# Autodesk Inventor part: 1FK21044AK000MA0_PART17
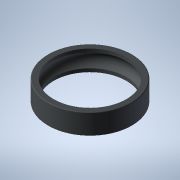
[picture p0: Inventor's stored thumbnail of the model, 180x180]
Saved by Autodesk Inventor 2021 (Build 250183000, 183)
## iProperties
Created: 2025-04
Part Number: 1FK21044AK000MA0_PART17
Material: Generic
Catalog Web Link: www.3dfindit.com
Description: -Servo synchronous motor
Document SubType Name: Modeling
Designer: psAdmin
Mass: 1.64389 g
Surface Area: 26.4305 cm^2
Volume: 1.64389 cm^3
Density: 1 g/cm^3
Appearance: PSOLRGB-212-217-219
Category: PARTsolutions
Title: 1FK21044AK000MA0_PART17
Author: Cadenas PARTsolutions
Comments: Servo synchronous motor
Sending System: PARTsolutions
Preprocessor: ST-DEVELOPER v19.3
PSOL_IDENT_0: {$CADENAS_DATA/23d-libs/siemens_ag/_cat_/87/f4/1fk21044ak000ma0.prj},216 {VTYP=3D},{NB=1FK21044AK000
PSOL_IDENT_1: MA0_PART17},{LINA=1FK21044AK000MA0_PART17},{NN=1FK21044AK000MA0_PART17},{NOPRJ=TRUE},{DATE=19.08.202
PSOL_IDENT_2: 5 14:00:48},{GEOMDATE=30.07.2025 02:00:50},{VERSION=},{LINEID=10},{WBVAR=},{WBNUMERIC=}  {NB=1FK2104
PSOL_IDENT_3: 4AK000MA0_PART17},{LINA=1FK21044AK000MA0_PART17},{KT=DUMMY},{PREVIEW=../../../_pool_/cb/72/p_d211_xx
PSOL_IDENT_4: _00434j.png},{DESCSHORT=SIMOTICS S-1FK2 HD, SINAMICS S210 3AC 400V-480V, 0.95 Nm, 6000 rpm},{DESCLON
PSOL_IDENT_5: G=SIMOTICS S-1FK2 HD servo motor M0=1.27 Nm; PN = 0.6 kW at nN=6000 rpm (380-480 V); PN = 0.4 kW at
PSOL_IDENT_6: nN=3000 rpm (200-240 V); degree of protection IP64; cylindrical shaft D19x40mm; absolute encoder 22-
PSOL_IDENT_7: bit + 12-bit multiturn (encoder AM22DQC); with OCC interface; plug size M17, rotatable; SIMOTICS S-1
PSOL_IDENT_8: FK2 servomotorfor a wide range of uses in industrial environments. SIMOTICS S‑1FK2 servomotors are c
PSOL_IDENT_9: ompact synchronous motors with a high dynamic performance that set themselves apart as a result of t
PSOL_IDENT_10: heir high power density, degree of protection and overload capability. The motors are available in t
PSOL_IDENT_11: wo variants: as High Dynamic variant (highest dynamic performance as a result of the low intrinsic m
PSOL_IDENT_12: oment of inertia for applications demanding a high dynamic performance with low moved masses) - and
PSOL_IDENT_13: as Compact variant (precise and stable closed-loop control for medium up to large moved masses as a
PSOL_IDENT_14: result of a medium intrinsic moment of inertia). SIMOTICSS‑1FK2 servomotors fully exploit their stre
PSOL_IDENT_15: ngths in a system with the SINAMICSS210 frequency converter and simple connection using the one cabl
PSOL_IDENT_16: e connection (OCC). Advantages include the short control and positioning times, fast and precise cor
PSOL_IDENT_17: rection of disturbing quantities as well as stable control with a high dynamic performance. The serv
PSOL_IDENT_18: o motors can be configured to address a wide range of requirements. For example with and without hol
PSOL_IDENT_19: ding brake, IP64 or IP65 degree of protection, singleturn or multiturn absolute encoders - to name j
PSOL_IDENT_20: ust a few. Further, the servomotors are available in different shaft heights extending from 20 to 10
PSOL_IDENT_21: 0. A shaft sealing ring is available to achieve an IP65 degree of protection and for subsequent moun
PSOL_IDENT_22: ting at the motor or as spare part. SIMOTICS - the optimum motor for each and every motion control a
PSOL_IDENT_23: pplication.},{INTNO=195125056312},{SUPPLIERALTNO=1FK2104-4AK00-0MA0},{MANUID=1FK21044AK000MA0},{MANU
PSOL_IDENT_24: NAME=Siemens},{MANUTYPEDESC=Synchronous motor 1FK2-HD 1,27 Nm},{AAU732=SIMOTICS},{AAO057=S-1FK2},{AA
PSOL_IDENT_25: U734=SIMOTICS S-1FK2 HD servo motor M0=1.27 Nm; PN = 0.6 kW at nN=6000 rpm (380-480 V); PN = 0.4 kW
PSOL_IDENT_26: at nN=3000 rpm (200-240 V); degree of protection IP64; cylindrical shaft D19x40mm; absolute encoder
PSOL_IDENT_27: 22-bit + 12-bit multiturn (encoder AM22DQC); with OCC interface; plug size M17, rotatable;},{AAW338=
PSOL_IDENT_28: Synchronous motor 1FK2-HD 1,27 Nm},{AAO742=SIMOTICS},{AAO663=4042948690994},{NOCUPEROU=1},{PRICEQUAN
PSOL_IDENT_29: TITY=1},{QUANTITYMIN=1},{QUANTITYINT=1},{CTN=85015100},{COO=DE},{AAO676=1FK2104-4AK00-0MA0},{AAO677=
PSOL_IDENT_30: Siemens AG},{ORDERUNIT=C62},{CONTENTUNIT=C62}
NB: 1FK21044AK000MA0_PART17
NT: Servo synchronous motor
NBSYN: $MANUID._PART17
LINA: 1FK21044AK000MA0_PART17
CATALOG: SIEMENS
PREVIEW: ../../../_pool_/cb/72/p_d211_xx_00434j.png
DESCSHORT: SIMOTICS S-1FK2 HD, SINAMICS S210 3AC 400V-480V, 0.95 Nm, 6000 rpm
DESCLONG: SIMOTICS S-1FK2 HD servo motor M0=1.27 Nm; PN = 0.6 kW at nN=6000 rpm (380-480 V); PN = 0.4 kW at nN=3000 rpm (200-240 V); degree of protection IP64; cylindrica
INTNO: 195125056312
SUPPLIERALTNO: 1FK2104-4AK00-0MA0
MANUID: 1FK21044AK000MA0
MANUNAME: Siemens
MANUTYPEDESC: Synchronous motor 1FK2-HD 1,27 Nm
AAU732: SIMOTICS
AAO057: S-1FK2
AAU734: SIMOTICS S-1FK2 HD servo motor M0=1.27 Nm; PN = 0.6 kW at nN=6000 rpm (380-480 V); PN = 0.4 kW at nN=3000 rpm (200-240 V); degree of protection IP64; cylindrica
AAW338: Synchronous motor 1FK2-HD 1,27 Nm
AAO742: SIMOTICS
AAO663: 4042948690994.0
NOCUPEROU: 1
PRICEQUANTITY: 1
QUANTITYMIN: 1
QUANTITYINT: 1
CTN: 85015100
COO: DE
ARTICLENO: 1FK21044AK000MA0_PART17
BOMINFO: 1FK21044AK000MA0_PART17
CREATOR: CADENAS GmbH
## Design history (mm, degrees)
feature "2025_04_17_15_37_40_0588"
body "Solid1"
